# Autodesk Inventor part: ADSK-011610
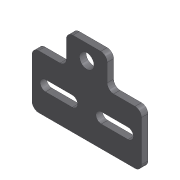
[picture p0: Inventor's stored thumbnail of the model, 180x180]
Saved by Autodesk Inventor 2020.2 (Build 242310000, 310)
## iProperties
Created: 2000-02
Part Number: ADSK-011610
Material: 1.0312 DC05
Document SubType Name: Blech
Description: PLT-21,FH,AX,02,040,031,NN6,SHAFT MOUNT PLATE
Designer: sspink
Density: 1 g/cm^3
Appearance: Metal-Steel(Polish)
Mass: 32.1113 g
Surface Area: 139.776 cm^2
Volume: 32.1113 cm^3
Sheet Metal Rule: Stahlblech 1.0312 - DC05 -   6.0 mm
Flat Pattern Width: 7.85 cm
Flat Pattern Length: 10.2 cm
Flat Pattern Area: 80.07 cm^2
Sheet Metal Width: 78,500 mm
Sheet Metal Length: 102,000 mm
Sheet Metal Area: 8007,000 mm^2
Control State: 0
Checked Out: False
Master: False
Shininess: 0.0
Length Units: 11269
Angle Units: 11279
Time Units: 11290
Mass Units: 11283
Length Display Precision: 3
Angle Display Precision: 2
Compacted: True
Cutlength: 3.13
Material Desc: FLAT,HRS,0.250X04.000
Material_Number: A084338
Dimensions: 78,5x6x102 mm
Mass: 0,032 kg
Semi finished: Stahlblech 1.0312 - DC05 -   6.0 mm
VLT_Material: 1.0312 DC05
G_L: 78,5x102 mm
Thickness: 6,000 mm
Density: 0.0
Volumn: 0.0
Area: 0.0
PropertySet Name: Model Information
Author: sspink
Revision Number: -
Title: PLT-21,FH,AX,02,040,031,NN6,SHAFT MOUNT PLATE
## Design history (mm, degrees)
node "Solide1"
  node "Extrusion1" dims "d5" = 6 (= Stärke), "d6" = 0
  node "Hole1" dims "d7" = 13.5, "d8" = 9.525, "d9" = 6.35, "d10" = 60 deg, "d11" = 19.05, "d12" = 118 deg, "d22" = 6
  node "Extrusion2" dims "d19" = 9.525, "d20" = 0
  node "Fillet1" dims "d21" = 6
sketch "Sketch1"
  geometry: L1 (0, 0)-(102, 0); L2 (102, 0)-(102, 50); L3 (102, 50)-(0, 50); L4 (0, 50)-(0, 0); L5 (51, 0)-(51, 50); L6 (32, 50)-(32, 78.5); L7 (32, 78.5)-(70, 78.5); L8 (70, 78.5)-(70, 50)
  constraints: 16 end point, 3 parallel, 3 perpendicular, 2 midpoint, 2 point on line, 1 horizontal
  dimensions: "d0" = 102 distance of L1.start L1.end; "d1" = 50 distance of L3.end L1.start; "d2" = 28.5 distance between parallel lines of L3 L7; "d3" = 38 distance between parallel lines of L8 L6; "d4" = 19 distance between parallel lines of L5 L6 (= 0.5 x d3)
sketch "Sketch3"
  geometry: L1 (0, 0)-(0, 50) reference; L2 (12.5, 20)-(37.5, 20); L3 (37.5, 20)-(37.5, 30); L4 (37.5, 30)-(12.5, 30); L5 (12.5, 30)-(12.5, 20); L6 (64.5, 20)-(89.5, 20); L7 (89.5, 20)-(89.5, 30); L8 (89.5, 30)-(64.5, 30); L9 (64.5, 30)-(64.5, 20); L10 (12.5, 25)-(37.5, 25); L11 (64.5, 25)-(89.5, 25); L12 (102, 0)-(0, 0) reference; L13 (37.5, 25)-(64.5, 25); A1 r 5 centre (12.5, 25) between (12.5, 30) and (12.5, 20); A2 r 5 centre (37.5, 25) between (37.5, 20) and (37.5, 30); A3 r 5 centre (64.5, 25) between (64.5, 30) and (64.5, 20); A4 r 5 centre (89.5, 25) between (89.5, 20) and (89.5, 30); 9 further points
  constraints: 22 end point, 9 midpoint, 8 point on circle, 4 centre point, 4 horizontal, 4 parallel, 4 tangent, 3 perpendicular, 2 horizontal alignment, 1 collinear, 1 equal radius, 1 vertical alignment
  dimensions: "d13" = 25 distance of L3.end L4.end; "d23" = 52 distance of point (77, 25) point (25, 25); "d24" = 10 distance between parallel lines of L2 L4
node "Corps solides"
node "Corps surfaciques"
sketch "Sketch2"
  geometry: L1 (70, 78.5)-(70, 50) reference; L2 (32, 78.5)-(70, 78.5) reference; L3 (32, 50)-(32, 78.5) reference; L4 (102, 0)-(0, 0) reference; L5 (32, 64.25)-(70, 64.25); L6 (51, 78.5)-(51, 0); 1 further point
  constraints: 5 midpoint, 4 end point, 1 point on line
feature "Definition1"
other parameters: "Stärke" = 6 (derived), "KFaktor" = 4.4, "Biegeradius" = 6 (= Stärke), "BreiteBiegungsfreistellung" = 6 (= Stärke), "TiefeBiegungsfreistellung" = 3 (= 0.5 x Stärke), "GrößeEckenfreistellung" = 24 (= 4 x Stärke), "AbstandVerbindung" = 0.01, "MinimalRest" = 12 (= 2 x Stärke), "Übergangsradius" = 6 (= Biegeradius), "JacobiRadiusGröße" = 6 (= Biegeradius), "Abstandsgröße" = 6 (= Stärke), "Abstandsgröße" = 6, "Biegeradius" = 6, "BreiteBiegungsfreistellung" = 6, "GrößeEckenfreistellung" = 24, "JacobiRadiusGröße" = 6, "MinimalRest" = 12, "Stärke" = 6, "TiefeBiegungsfreistellung" = 3, "Übergangsradius" = 6
